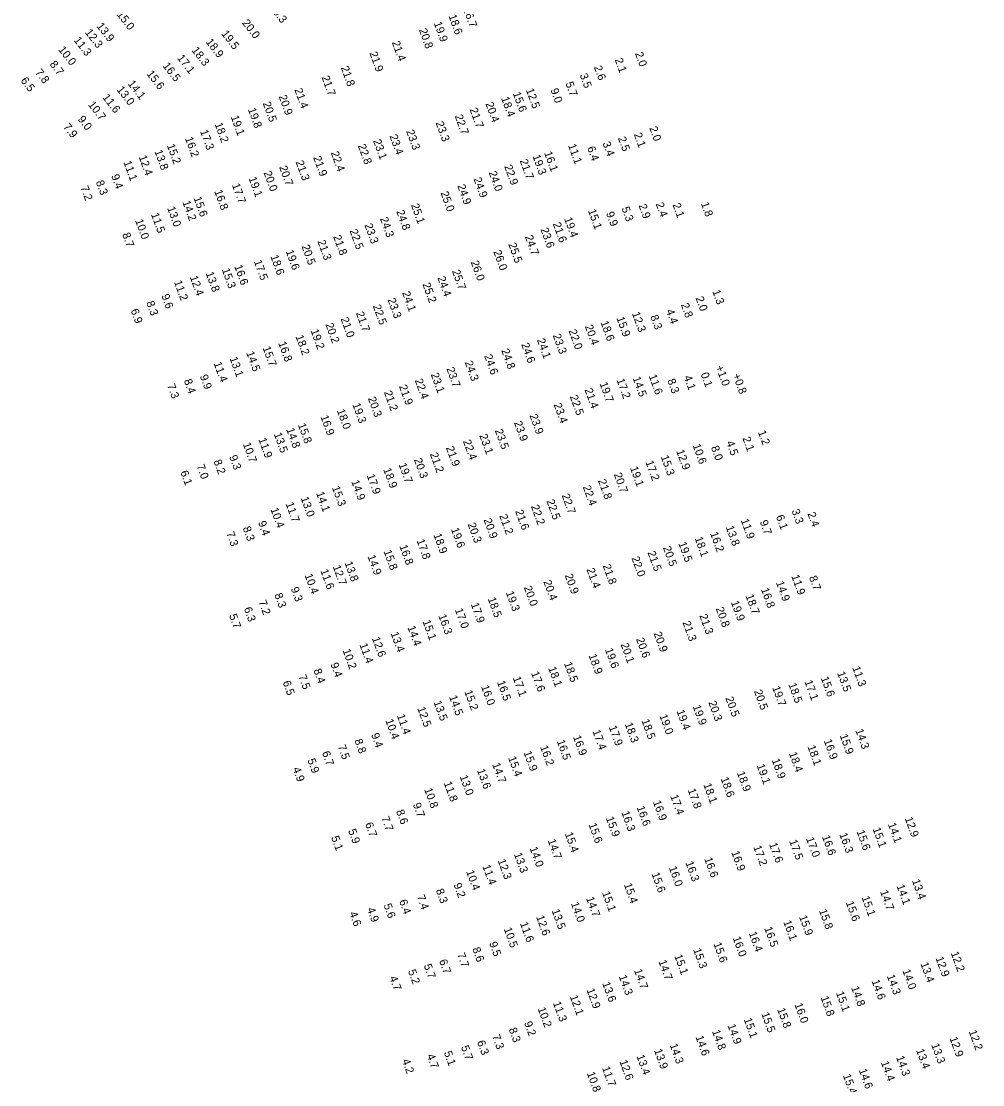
# Model space of a CAD drawing. Extents: x 815385 to 820851, y 582449 to 604245.
# Drawn here: x 819674 to 820275, y 592474 to 593138 of the extents above; entities that cross this region are included whole.
import ezdxf

# ---------------------------------------------------------------- set-up
doc = ezdxf.new("R2010")
doc.units = 0
doc.layers.add('V-TOPO-SOUN-112008', color=7, linetype='Continuous')

msp = doc.modelspace()

# ---------------------------------------------------------------- texts
at = {"layer": 'V-TOPO-SOUN-112008'}
for s, rotation, p in [('15.0 ', 307.782, (819733.8, 593142.38)), ('20.3 ', 307.782, (819829.14, 593146.78)), ('16.7 ', 289.902, (819950.57, 593145.92)), ('13.9 ', 307.782, (819721.19, 593135.04)), ('20.0 ', 307.782, (819812.22, 593137.04)), ('19.9 ', 289.902, (819932.27, 593136.98)), ('18.6 ', 289.902, (819941.42, 593141.51)), ('12.3 ', 307.782, (819713.98, 593131.12)), ('19.5 ', 307.782, (819799.25, 593130.26)), ('20.8 ', 289.902, (819922.99, 593132.76)), ('11.3 ', 307.782, (819706.96, 593126.23)), ('18.9 ', 307.782, (819789.52, 593125.13)), ('21.4 ', 289.902, (819906.03, 593124.93)), ('10.0 ', 307.782, (819697.36, 593120.33)), ('17.1 ', 307.782, (819771.62, 593115.11)), ('18.3 ', 307.782, (819780.64, 593119.95)), ('21.9 ', 289.902, (819892.02, 593118.26)), ('2.0', 289.902, (820058.02, 593118.03)), ('8.7', 307.782, (819691.88, 593111.16)), ('16.5 ', 307.782, (819762.58, 593110.2)), ('2.6', 289.902, (820032.35, 593109.5)), ('2.1', 289.902, (820045.35, 593114.24)), ('7.8', 307.782, (819682.85, 593106.05)), ('15.6 ', 307.782, (819752.5, 593105.23)), ('21.7 ', 289.902, (819862.08, 593103.2)), ('21.8 ', 289.902, (819874.15, 593109.19)), ('3.5', 289.902, (820023.45, 593104.6)), ('6.5', 307.782, (819673.76, 593100.97)), ('13.0 ', 307.782, (819733.82, 593095.36)), ('14.1 ', 307.782, (819740.74, 593099.05)), ('5.7', 289.902, (820014.54, 593099.4)), ('11.6 ', 307.782, (819724.89, 593090.53)), ('20.9 ', 289.902, (819835.28, 593091.2)), ('21.4 ', 289.902, (819845.11, 593095.38)), ('18.4 ', 289.902, (819974.33, 593090.09)), ('15.6 ', 289.902, (819981.62, 593093.14)), ('12.5 ', 289.902, (819989.83, 593095.33)), ('9.0', 289.902, (820005.18, 593095.3)), ('10.7 ', 307.782, (819715.93, 593085.95)), ('19.8 ', 289.902, (819816.04, 593083.12)), ('20.5 ', 289.902, (819825.31, 593086.93)), ('21.7 ', 289.902, (819954.66, 593083.11)), ('20.4 ', 289.902, (819964.52, 593086.69)), ('9.0', 307.782, (819709.48, 593076.84)), ('19.1 ', 289.902, (819805.33, 593078.42)), ('22.7 ', 289.902, (819945.34, 593078.93)), ('7.9', 307.782, (819700.39, 593072.08)), ('18.2 ', 289.902, (819795.25, 593073.94)), ('23.3 ', 289.902, (819933.39, 593074.69)), ('2.0', 289.902, (820066.99, 593071.47)), ('16.2 ', 289.902, (819776.72, 593065.01)), ('17.3 ', 289.902, (819786.13, 593069.46)), ('23.1 ', 289.902, (819894.34, 593063.46)), ('23.4 ', 289.902, (819904.55, 593066.44)), ('23.3 ', 289.902, (819914.96, 593069.46)), ('2.5', 289.902, (820047.36, 593065.14)), ('2.1', 289.902, (820057.29, 593067.54)), ('13.8 ', 289.902, (819757.61, 593056.91)), ('15.2 ', 289.902, (819765.39, 593060.61)), ('22.8 ', 289.902, (819884.79, 593060.42)), ('11.1 ', 289.902, (820016.16, 593060.63)), ('6.4', 289.902, (820028.09, 593059.08)), ('3.4', 289.902, (820037.71, 593062.03)), ('11.1 ', 289.902, (819738.23, 593050.1)), ('12.4 ', 289.902, (819747.75, 593053.48)), ('21.3 ', 289.902, (819845.89, 593050.26)), ('21.9 ', 289.902, (819856.86, 593053.01)), ('22.4 ', 289.902, (819867.88, 593055.97)), ('21.7 ', 289.902, (819985.99, 593051.05)), ('19.3 ', 289.902, (819993.92, 593053.9)), ('16.1 ', 289.902, (820001.22, 593055.91)), ('20.0 ', 289.902, (819825.84, 593043.6)), ('20.7 ', 289.902, (819835.57, 593047.02)), ('24.0 ', 289.902, (819966.56, 593043.63)), ('22.9 ', 289.902, (819976.25, 593047.5)), ('8.3', 289.902, (819720.99, 593037.79)), ('9.4', 289.902, (819730.56, 593041.6)), ('19.1 ', 289.902, (819816.48, 593040.05)), ('24.9 ', 289.902, (819957.08, 593039.64)), ('7.2', 289.902, (819711.39, 593034.36)), ('16.8 ', 289.902, (819795.02, 593031.9)), ('17.7 ', 289.902, (819806.05, 593035.93)), ('25.0 ', 289.902, (819936.45, 593030.93)), ('24.9 ', 289.902, (819946.96, 593035.31)), ('14.2 ', 289.902, (819775.1, 593025.17)), ('15.6 ', 289.902, (819782.08, 593027.69)), ('25.1 ', 289.902, (819917.98, 593023.31)), ('2.9', 289.902, (820060.27, 593023.07)), ('2.4', 289.902, (820070.95, 593024.04)), ('2.1', 289.902, (820081.48, 593023.63)), ('1.8', 289.902, (820099.27, 593024.27)), ('11.5 ', 289.902, (819755.46, 593017.53)), ('13.0 ', 289.902, (819765.57, 593021.44)), ('24.8 ', 289.902, (819908.79, 593019.33)), ('15.1 ', 289.902, (820028.65, 593019.84)), ('9.9', 289.902, (820039.89, 593018.25)), ('5.3', 289.902, (820049.61, 593021.3)), ('10.0 ', 289.902, (819745.52, 593013.65)), ('23.3 ', 289.902, (819888.93, 593010.85)), ('24.3 ', 289.902, (819898.61, 593014.87)), ('21.6 ', 289.902, (820006.66, 593011.6)), ('19.4 ', 289.902, (820013.72, 593014.76)), ('8.7', 289.902, (819737.43, 593005.13)), ('21.8 ', 289.902, (819869.35, 593003.63)), ('22.5 ', 289.902, (819879.57, 593007.3)), ('24.7 ', 289.902, (819989.22, 593003.56)), ('23.6 ', 289.902, (819998.95, 593008.17)), ('20.5 ', 289.902, (819849.6, 592997.6)), ('21.3 ', 289.902, (819859.52, 593000.6)), ('25.5 ', 289.902, (819978.83, 592998.79)), ('18.6 ', 289.902, (819830.09, 592991.26)), ('19.6 ', 289.902, (819839.64, 592994.44)), ('26.0 ', 289.902, (819969.46, 592994.18)), ('16.6 ', 289.902, (819807.5, 592985.04)), ('17.5 ', 289.902, (819819.76, 592988.09)), ('26.0 ', 289.902, (819955.34, 592987.66)), ('12.4 ', 289.902, (819779.74, 592978.3)), ('13.8 ', 289.902, (819789.65, 592980.75)), ('15.3 ', 289.902, (819799.73, 592982.95)), ('24.4 ', 289.902, (819934.5, 592977.83)), ('25.7 ', 289.902, (819943.62, 592982.01)), ('11.2 ', 289.902, (819769.83, 592975.3)), ('25.2 ', 289.902, (819925.14, 592973.88)), ('9.6', 289.902, (819761.92, 592966.74)), ('23.3 ', 289.902, (819903.35, 592964.22)), ('24.1 ', 289.902, (819912.44, 592968.48)), ('2.0', 289.902, (820095.9, 592965.25)), ('1.3', 289.902, (820106.34, 592969.43)), ('6.9', 289.902, (819742.74, 592957.52)), ('8.3', 289.902, (819752.47, 592962.37)), ('22.5 ', 289.902, (819894.14, 592960.2)), ('4.4', 289.902, (820077.44, 592957.26)), ('2.8', 289.902, (820086.73, 592961.12)), ('21.0 ', 289.902, (819874, 592952.25)), ('21.7 ', 289.902, (819883.56, 592955.82)), ('15.9 ', 289.902, (820046.39, 592952.72)), ('12.3 ', 289.902, (820056.1, 592955.64)), ('8.3', 289.902, (820067.55, 592953.75)), ('19.2 ', 289.902, (819855.23, 592944.86)), ('20.2 ', 289.902, (819864.47, 592948.7)), ('22.0 ', 289.902, (820016.5, 592944.74)), ('20.4 ', 289.902, (820026.67, 592947.59)), ('18.6 ', 289.902, (820036.47, 592950.02)), ('16.8 ', 289.902, (819835.02, 592937.11)), ('18.2 ', 289.902, (819845.79, 592941.23)), ('24.1 ', 289.902, (819996.73, 592939.06)), ('23.3 ', 289.902, (820006.61, 592941.93)), ('14.5 ', 289.902, (819815.01, 592931.04)), ('15.7 ', 289.902, (819825.22, 592934.12)), ('24.8 ', 289.902, (819974.4, 592932.53)), ('24.6 ', 289.902, (819986.88, 592936.29)), ('11.4 ', 289.902, (819794.6, 592924.43)), ('13.1 ', 289.902, (819804.61, 592927.58)), ('24.3 ', 289.902, (819951.58, 592925.03)), ('24.6 ', 289.902, (819963.74, 592929.06)), ('23.1 ', 289.902, (819930.35, 592917.56)), ('23.7 ', 289.902, (819940.13, 592921.07)), ('0.1', 289.902, (820099.08, 592917.74)), ('+1.0 ', 289.902, (820108.47, 592922.16)), ('7.3', 289.902, (819765.56, 592910.64)), ('8.4', 289.902, (819775.99, 592913.66)), ('9.9', 289.902, (819786.01, 592916.41)), ('22.4 ', 289.902, (819920.35, 592913.83)), ('19.7 ', 289.902, (820035.88, 592911.75)), ('17.2 ', 289.902, (820046.49, 592914.03)), ('14.5 ', 289.902, (820056.58, 592915.2)), ('11.6 ', 289.902, (820066.59, 592916.58)), ('8.3', 289.902, (820078.22, 592913.82)), ('4.1', 289.902, (820088.53, 592915.96)), ('+0.8 ', 289.902, (820119.05, 592917.11)), ('21.2 ', 289.902, (819901.08, 592906.38)), ('21.9 ', 289.902, (819910.5, 592910.05)), ('22.5 ', 289.902, (820017.28, 592903.66)), ('21.4 ', 289.902, (820026.49, 592907.93)), ('19.3 ', 289.902, (819881.33, 592898.72)), ('20.3 ', 289.902, (819891.04, 592902.53)), ('23.4 ', 289.902, (820007.17, 592898.67)), ('16.9 ', 289.902, (819861.38, 592891.09)), ('18.0 ', 289.902, (819871.66, 592894.95)), ('23.9 ', 289.902, (819992.1, 592891.82)), ('15.8 ', 289.902, (819847.27, 592886.06)), ('23.9 ', 289.902, (819982.36, 592887.44)), ('13.5 ', 289.902, (819832.25, 592880.22)), ('14.8 ', 289.902, (819840.03, 592883.17)), ('23.1 ', 289.902, (819960.72, 592879.31)), ('23.5 ', 289.902, (819970.4, 592882.47)), ('2.1', 289.902, (820125.18, 592877.64)), ('1.2', 289.902, (820134.91, 592881.54)), ('10.7 ', 289.902, (819812.87, 592874.03)), ('11.9 ', 289.902, (819822.58, 592876.94)), ('21.9 ', 289.902, (819939.81, 592871.74)), ('22.4 ', 289.902, (819950.47, 592875.76)), ('10.6 ', 289.902, (820094.08, 592873.18)), ('8.0', 289.902, (820105.5, 592871.91)), ('4.5', 289.902, (820115.08, 592875.02)), ('9.3', 289.902, (819804.33, 592866.1)), ('20.3 ', 289.902, (819919.82, 592864.28)), ('21.2 ', 289.902, (819929.81, 592867.73)), ('15.3 ', 289.902, (820074.11, 592866.04)), ('12.9 ', 289.902, (820083.8, 592869.59)), ('7.0', 289.902, (819783.98, 592860.31)), ('8.2', 289.902, (819794.54, 592863.3)), ('18.9 ', 289.902, (819900.64, 592858.12)), ('19.7 ', 289.902, (819910.25, 592861.22)), ('19.1 ', 289.902, (820054.91, 592859.11)), ('17.2 ', 289.902, (820064.57, 592862.75)), ('6.1', 289.902, (819773.8, 592856.46)), ('14.9 ', 289.902, (819880.63, 592850.6)), ('17.9 ', 289.902, (819890.31, 592854.34)), ('21.8 ', 289.902, (820034.92, 592851.11)), ('20.7 ', 289.902, (820044.78, 592855.1)), ('15.3 ', 289.902, (819868.56, 592846.82)), ('22.4 ', 289.902, (820025.39, 592847.2)), ('13.0 ', 289.902, (819849.04, 592840.19)), ('14.1 ', 289.902, (819858.66, 592843.33)), ('22.5 ', 289.902, (820002.64, 592838.43)), ('22.7 ', 289.902, (820012.18, 592841.98)), ('10.4 ', 289.902, (819830.12, 592833.26)), ('11.7 ', 289.902, (819839.62, 592836.72)), ('21.6 ', 289.902, (819983.13, 592832.03)), ('22.2 ', 289.902, (819992.98, 592835.06)), ('3.3', 289.902, (820155.88, 592832.34)), ('2.4', 289.902, (820165.86, 592830.46)), ('9.4', 289.902, (819822.38, 592824.97)), ('20.3 ', 289.902, (819953.43, 592823.9)), ('20.9 ', 289.902, (819963.37, 592826.65)), ('21.2 ', 289.902, (819973.17, 592829.19)), ('11.9 ', 289.902, (820124.15, 592826.42)), ('9.7', 289.902, (820136.01, 592825.51)), ('6.1', 289.902, (820146.17, 592828.74)), ('7.3', 289.902, (819802.53, 592818.29)), ('8.3', 289.902, (819812.83, 592821.55)), ('19.6 ', 289.902, (819942.99, 592820.79)), ('16.2 ', 289.902, (820104.97, 592818.2)), ('13.8 ', 289.902, (820114.78, 592822.07)), ('17.8 ', 289.902, (819921.47, 592813.67)), ('18.9 ', 289.902, (819932.03, 592817.22)), ('19.5 ', 289.902, (820085.14, 592811.92)), ('18.1 ', 289.902, (820095.32, 592815.17)), ('15.8 ', 289.902, (819900.85, 592806.94)), ('16.8 ', 289.902, (819910.73, 592810.17)), ('21.5 ', 289.902, (820065.86, 592806.21)), ('20.5 ', 289.902, (820075.47, 592809.29)), ('12.7 ', 289.902, (819869.08, 592797.39)), ('13.8 ', 289.902, (819876.43, 592799.74)), ('14.9 ', 289.902, (819890.81, 592803.82)), ('21.8 ', 289.902, (820037.84, 592797.96)), ('22.0 ', 289.902, (820055.78, 592802.81)), ('10.4 ', 289.902, (819851.48, 592792.03)), ('11.6 ', 289.902, (819861.29, 592794.9)), ('20.9 ', 289.902, (820014.1, 592791.96)), ('21.4 ', 289.902, (820027.73, 592795.61)), ('11.9 ', 289.902, (820155.75, 592791.43)), ('8.7', 289.902, (820166.8, 592790.72)), ('20.0 ', 289.902, (819988.5, 592784.44)), ('20.4 ', 289.902, (820000.75, 592788.01)), ('14.9 ', 289.902, (820146.15, 592787.46)), ('8.3', 289.902, (819832.58, 592779.85)), ('9.3', 289.902, (819842.83, 592783.71)), ('19.3 ', 289.902, (819977.28, 592781.2)), ('18.7 ', 289.902, (820127.14, 592779.2)), ('16.8 ', 289.902, (820136.78, 592783.22)), ('6.3', 289.902, (819813.48, 592771.17)), ('7.2', 289.902, (819822.67, 592775.44)), ('17.9 ', 289.902, (819955.38, 592773.94)), ('18.5 ', 289.902, (819965.97, 592777.32)), ('20.8 ', 289.902, (820108.51, 592771.21)), ('19.9 ', 289.902, (820117.96, 592775.16)), ('5.7', 289.902, (819804.25, 592766.87)), ('16.3 ', 289.902, (819935.09, 592766.72)), ('17.0 ', 289.902, (819945.44, 592770.45)), ('21.3 ', 289.902, (820098.25, 592766.82)), ('14.4 ', 289.902, (819915.76, 592759.51)), ('15.1 ', 289.902, (819925.19, 592763.18)), ('21.3 ', 289.902, (820087.74, 592762.49)), ('12.6 ', 289.902, (819893.57, 592752.57)), ('13.4 ', 289.902, (819905.25, 592755.7)), ('20.6 ', 289.902, (820058.67, 592752.11)), ('20.9 ', 289.902, (820069.69, 592755.71)), ('10.2 ', 289.902, (819875.24, 592745.06)), ('11.4 ', 289.902, (819885.78, 592748.63)), ('19.6 ', 289.902, (820039.25, 592745.57)), ('20.1 ', 289.902, (820049.02, 592748.79)), ('18.9 ', 289.902, (820029.03, 592741.91)), ('8.4', 289.902, (819857.03, 592732.65)), ('9.4', 289.902, (819867.63, 592736.45)), ('17.6 ', 289.902, (819993.08, 592730.94)), ('18.1 ', 289.902, (820003.78, 592733.98)), ('18.5 ', 289.902, (820013.67, 592736.89)), ('13.5 ', 289.902, (820184.4, 592730.91)), ('11.3 ', 289.902, (820193.86, 592734.21)), ('6.5', 289.902, (819837.76, 592725.2)), ('7.5', 289.902, (819847.6, 592728.9)), ('16.5 ', 289.902, (819971.77, 592725.24)), ('17.1 ', 289.902, (819981.63, 592727.86)), ('17.1 ', 289.902, (820163.97, 592725.53)), ('15.6 ', 289.902, (820174.16, 592727.78)), ('15.2 ', 289.902, (819951.31, 592719.29)), ('16.0 ', 289.902, (819961.79, 592722.42)), ('20.5 ', 289.902, (820132.43, 592719.55)), ('19.7 ', 289.902, (820143.79, 592721.83)), ('18.5 ', 289.902, (820153.91, 592723.82)), ('13.5 ', 289.902, (819932.13, 592712.72)), ('14.5 ', 289.902, (819941.8, 592716.05)), ('20.3 ', 289.902, (820103.87, 592712.56)), ('20.5 ', 289.902, (820114.54, 592715.25)), ('12.5 ', 289.902, (819921.94, 592708.87)), ('19.4 ', 289.902, (820083.99, 592707.1)), ('19.9 ', 289.902, (820094.13, 592710.07)), ('10.4 ', 289.902, (819901.94, 592701.28)), ('11.4 ', 289.902, (819909.17, 592704.29)), ('18.3 ', 289.902, (820051.63, 592699.07)), ('18.5 ', 289.902, (820062.04, 592701.19)), ('19.0 ', 289.902, (820073.26, 592704.24)), ('9.4', 289.902, (819893.05, 592692.45)), ('16.9 ', 289.902, (820019.26, 592691.04)), ('17.4 ', 289.902, (820031.42, 592694.55)), ('17.9 ', 289.902, (820041.64, 592697.15)), ('15.9 ', 289.902, (820185.99, 592691.84)), ('14.3 ', 289.902, (820195.78, 592695.09)), ('7.5', 289.902, (819872.2, 592685.11)), ('8.8', 289.902, (819882.6, 592688.83)), ('16.2 ', 289.902, (819998.7, 592684.73)), ('16.5 ', 289.902, (820009.13, 592688.3)), ('18.1 ', 289.902, (820165.86, 592684.85)), ('16.9 ', 289.902, (820176.03, 592688.62)), ('6.7', 289.902, (819862.34, 592681.18)), ('15.4 ', 289.902, (819978.71, 592677.92)), ('15.9 ', 289.902, (819988.36, 592681.29)), ('18.4 ', 289.902, (820154.25, 592680.68)), ('5.9', 289.902, (819853.23, 592676.54)), ('14.7 ', 289.902, (819968.75, 592673.88)), ('19.1 ', 289.902, (820134.09, 592673.16)), ('18.9 ', 289.902, (820143.52, 592676.58)), ('4.9', 289.902, (819844.03, 592671.19)), ('13.0 ', 289.902, (819948.43, 592666.17)), ('13.6 ', 289.902, (819959.26, 592670.16)), ('18.6 ', 289.902, (820111.55, 592664.97)), ('18.9 ', 289.902, (820121.73, 592668.59)), ('10.8 ', 289.902, (819926.21, 592658.16)), ('11.8 ', 289.902, (819938.48, 592662.22)), ('17.8 ', 289.902, (820090.97, 592657.86)), ('18.1 ', 289.902, (820100.75, 592661.17)), ('17.4 ', 289.902, (820080.06, 592654.02)), ('8.6', 289.902, (819908.67, 592644.58)), ('9.7', 289.902, (819919.15, 592648.86)), ('16.6 ', 289.902, (820059.08, 592646.97)), ('16.9 ', 289.902, (820069.23, 592650.38)), ('7.7', 289.902, (819899.46, 592640.35)), ('15.9 ', 289.902, (820039.84, 592640.29)), ('16.3 ', 289.902, (820049.53, 592643.72)), ('12.9 ', 289.902, (820226.67, 592640.05)), ('5.9', 289.902, (819878.69, 592632.5)), ('6.7', 289.902, (819889.27, 592636.65)), ('15.6 ', 289.902, (820029, 592636.27)), ('15.6 ', 289.902, (820196.52, 592631.88)), ('15.1 ', 289.902, (820206.56, 592633.52)), ('14.1 ', 289.902, (820216.15, 592636.47)), ('5.1', 289.902, (819868.07, 592628.17)), ('14.7 ', 289.902, (820003.47, 592626.25)), ('15.4 ', 289.902, (820014.15, 592630.49)), ('17.5 ', 289.902, (820154.39, 592625.9)), ('17.0 ', 289.902, (820164.97, 592627.51)), ('16.6 ', 289.902, (820174.91, 592628.66)), ('16.3 ', 289.902, (820185.73, 592630.15)), ('14.0 ', 289.902, (819992.14, 592621.41)), ('16.9 ', 289.902, (820118.25, 592618.88)), ('17.2 ', 289.902, (820131.99, 592622.23)), ('17.6 ', 289.902, (820141.85, 592624.02)), ('12.3 ', 289.902, (819972.18, 592613.74)), ('13.3 ', 289.902, (819982.36, 592617.74)), ('16.3 ', 289.902, (820089.53, 592612.37)), ('16.6 ', 289.902, (820101.29, 592614.81)), ('10.4 ', 289.902, (819952.45, 592606.86)), ('11.4 ', 289.902, (819962.62, 592610.21)), ('15.6 ', 289.902, (820068.34, 592605.42)), ('16.0 ', 289.902, (820079.16, 592609.29)), ('9.2', 289.902, (819944.57, 592598.72)), ('15.4 ', 289.902, (820051.09, 592598.69)), ('13.4 ', 289.902, (820231.16, 592601.15)), ('7.4', 289.902, (819921.66, 592591.31)), ('8.3', 289.902, (819933.51, 592595.2)), ('15.1 ', 289.902, (820037.43, 592593.57)), ('14.7 ', 289.902, (820211.22, 592594.3)), ('14.1 ', 289.902, (820221.52, 592597.88)), ('5.6', 289.902, (819900.86, 592585.91)), ('6.4', 289.902, (819910.55, 592588.43)), ('14.0 ', 289.902, (820017.94, 592586.9)), ('14.7 ', 289.902, (820027.43, 592590.21)), ('15.6 ', 289.902, (820189.84, 592587.49)), ('15.1 ', 289.902, (820199.67, 592590.65)), ('4.6', 289.902, (819879.42, 592580.87)), ('4.9', 289.902, (819890.45, 592583.47)), ('12.6 ', 289.902, (819996.21, 592578.56)), ('13.5 ', 289.902, (820005.9, 592582.48)), ('15.9 ', 289.902, (820160.56, 592578.64)), ('15.8 ', 289.902, (820173.04, 592582.47)), ('11.6 ', 289.902, (819986.11, 592574.46)), ('16.5 ', 289.902, (820138.79, 592571.46)), ('16.1 ', 289.902, (820150.7, 592575.46)), ('10.5 ', 289.902, (819976, 592571.01)), ('16.0 ', 289.902, (820119.09, 592565.38)), ('16.4 ', 289.902, (820129.13, 592568.4)), ('8.6', 289.902, (819956.28, 592558.61)), ('9.5', 289.902, (819966.85, 592562.08)), ('15.6 ', 289.902, (820107.07, 592561.7)), ('7.7', 289.902, (819946.78, 592555.15)), ('15.1 ', 289.902, (820082.59, 592554.14)), ('15.3 ', 289.902, (820094.38, 592558.01)), ('12.9 ', 289.902, (820245.9, 592552.82)), ('12.2 ', 289.902, (820255.41, 592555.95)), ('5.2', 289.902, (819916.11, 592544.71)), ('5.7', 289.902, (819925.92, 592548.14)), ('6.7', 289.902, (819935.53, 592551.08)), ('14.7 ', 289.902, (820057.42, 592545.12)), ('14.7 ', 289.902, (820072.7, 592550.72)), ('14.0 ', 289.902, (820225.18, 592544.91)), ('13.4 ', 289.902, (820236.44, 592549.28)), ('4.7', 289.902, (819904.47, 592540.7)), ('14.3 ', 289.902, (820047.9, 592541.35)), ('14.6 ', 289.902, (820205.94, 592538.47)), ('14.3 ', 289.902, (820215.44, 592541.61)), ('12.9 ', 289.902, (820027.71, 592532.94)), ('13.6 ', 289.902, (820037.52, 592537.01)), ('14.8 ', 289.902, (820193.14, 592534.31)), ('12.1 ', 289.902, (820017.28, 592528.77)), ('15.8 ', 289.902, (820174.04, 592528.14)), ('15.1 ', 289.902, (820183.67, 592531.08)), ('10.2 ', 289.902, (819997.19, 592521.17)), ('11.3 ', 289.902, (820006.74, 592524.78)), ('15.8 ', 289.902, (820146.88, 592520.76)), ('16.0 ', 289.902, (820157.7, 592523.81)), ('9.2', 289.902, (819988.67, 592512.29)), ('15.1 ', 289.902, (820126.02, 592514.52)), ('15.5 ', 289.902, (820136.99, 592517.99)), ('8.3', 289.902, (819979.1, 592508.32)), ('14.8 ', 289.902, (820106.17, 592507.08)), ('14.9 ', 289.902, (820115.87, 592510.7)), ('12.2 ', 289.902, (820266.67, 592506.93)), ('6.3', 289.902, (819959.25, 592500.42)), ('7.3', 289.902, (819968.69, 592504.04)), ('14.3 ', 289.902, (820079.7, 592498.49)), ('14.6 ', 289.902, (820095.86, 592503.48)), ('13.3 ', 289.902, (820243.21, 592498.58)), ('12.9 ', 289.902, (820254.64, 592502.71)), ('5.1', 289.902, (819938.56, 592493.77)), ('5.7', 289.902, (819949.24, 592497.23)), ('13.9 ', 289.902, (820069.93, 592495.15)), ('13.4 ', 289.902, (820233.75, 592495.25)), ('4.2', 289.902, (819912.36, 592488.83)), ('4.7', 289.902, (819927.82, 592491.94)), ('12.6 ', 289.902, (820048.29, 592488.21)), ('13.4 ', 289.902, (820058.95, 592491.53)), ('14.4 ', 289.902, (820211.74, 592487.57)), ('14.3 ', 289.902, (820221.22, 592490.83)), ('10.8 ', 289.902, (820027.94, 592480.84)), ('11.7 ', 289.902, (820037.41, 592484.19)), ('15.4 ', 289.902, (820187.99, 592479.46)), ('14.6 ', 289.902, (820197.95, 592482.8))]:
    msp.add_text(s, height=5, rotation=rotation, dxfattribs=at).set_placement(p)

doc.saveas('drawing.dxf')
